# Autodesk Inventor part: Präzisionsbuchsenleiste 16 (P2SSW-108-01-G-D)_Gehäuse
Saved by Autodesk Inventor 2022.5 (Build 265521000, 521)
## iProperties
Created: 2024-12
Part Number: Präzisionsbuchsenleiste 16 (P2SSW-108-01-G-D)_Gehäuse
Material: Generic
Document SubType Name: Modeling
Designer: AdminForWorker
Density: 1 g/cm^3
Appearance: Default
Title: Präzisionsbuchsenleiste 16 (P2SSW-108-01-G-D)_Gehäuse
Author: AdminForWorker
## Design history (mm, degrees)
feature "Body1"
body "Solid1"
